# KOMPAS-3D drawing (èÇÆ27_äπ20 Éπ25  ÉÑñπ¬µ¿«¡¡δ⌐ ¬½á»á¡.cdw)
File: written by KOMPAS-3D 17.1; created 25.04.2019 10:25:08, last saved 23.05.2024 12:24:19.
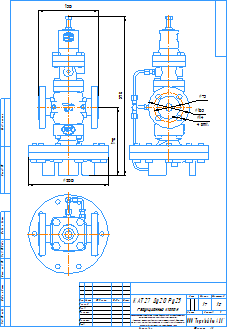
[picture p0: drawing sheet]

Sheet 1: A3, portrait

Title block, sheet 1: name: КАТ27 Ду20 Ру25 / Редукционный клапан; material: Сталь 10  ГОСТ 1050-2013; mass: 17; sheets: 1; sheet format: A3; stored path: D:\Документы\Компас\Поставщики\Armstrong\Редукционный клапан GP-2000\KOMPAS 2D\GP-2000 _ Ду20 Ру25  Редукционный клапан.cdw

Views: Вид 1
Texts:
  adm
  Рама для чертежей
  Лит-Масса-Масштаб
  Материал-Предприятие
  Масштаб
  Изм.
  Лист
  № докум.
  Подп.
  Дата
  Лит.
  Разраб.
  Пров.
  Т.контр.
  Листов
  Внимание! Данный продукт является объектом авторского права ООО «Торговый Дом АДЛ».
  Запрещается изменение, копирование, распространение
  (в том числе путем копирования на другие сайты и ресурсы в Интернете)
  или любое иное использование информации и объектов без предварительного
  согласия правообладателя (ООО «Торговый Дом АДЛ»).
  Н.контр.
  Утв.
  ООО "Торговый дом АДЛ"
  Изменение
  Номер документа
  Подпись
  Обозначение документа
  Наименование изделия
  Масса изделия по ГОСТ 2.109-73
  Порядковый номер листа
  Общее количество листов в документе
  Характер работы, выполненной лицом, подписавшим документ
  Наименование или индекс предприятия, выпускающего документ
  Инв. № подл.
  Подп. и дата
  Взам. инв. №
  Инв. № дубл.
  Инвентарный номер подлинника по ГОСТ 2.501-68
  Подпись принявшего подлинник в отдел технической документации
  Инвентарный номер подлинника, взамен которого выпущен данный подлинник
  Инвентарный номер дубликата по ГОСТ 2.502-68
  Подпись принявшего дубликат в отдел технической документации
  Справ. №
  Перв. примен.
  Обозначение документа, взамен или на основании которого выпущен данный документ
  Обозначение документа, в котором впервые записан данный документ
  Подпись лица, копировавшего чертеж
  Обозначение формата листа
  !Рама для чертежа
Dimensions and other numbers on the sheet: 170; 398; 150; 200; 105; 75; 14; 4 отв.; 1:2; 1; 17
